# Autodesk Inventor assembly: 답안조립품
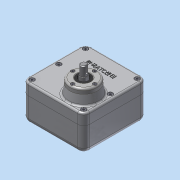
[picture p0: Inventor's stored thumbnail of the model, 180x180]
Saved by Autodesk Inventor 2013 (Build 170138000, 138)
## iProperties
Created: 2015-10
Part Number: 답안조립품
Document SubType Name: Assembly
Designer: dgall
Author: dgall
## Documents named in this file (15)
- C:\Users\dgall\Desktop\351007V1025\답안조립품.iam
- C:\Users\dgall\Desktop\351007V1025\본체.ipt
- C:\Users\dgall\Desktop\351007V1025\베어링 6002.ipt
- C:\Users\dgall\Desktop\351007V1025\오일실 15 x 25.ipt
- C:\Users\dgall\Desktop\351007V1025\로드 축.ipt
- C:\Users\dgall\Desktop\351007V1025\커버.ipt
- C:\Users\dgall\Desktop\351007V1025\베어링 6001.ipt
- C:\Users\dgall\Desktop\351007V1025\축 커버.ipt
- C:\Users\dgall\Desktop\351007V1025\오일실 12 x 22.ipt
- C:\Users\dgall\Desktop\351007V1025\편심 축.ipt
- C:\Users\dgall\Desktop\351007V1025\로드.ipt
- C:\Users\dgall\Desktop\351007V1025\슬라이드.ipt
- C:\Users\dgall\Desktop\351007V1025\M4 x 0.7.ipt
- C:\Users\dgall\Desktop\351007V1025\M3 x 0.5.ipt
- C:\Users\dgall\Desktop\351007V1025\스프링.ipt
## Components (10 placed, 2 different names)
1. M4 x 0.7:1
2. M4 x 0.7:2
3. M4 x 0.7:3
4. M4 x 0.7:4
5. M4 x 0.7:5
6. M4 x 0.7:6
7. M3 x 0.5:1
8. M3 x 0.5:2
9. M3 x 0.5:3
10. M3 x 0.5:4
